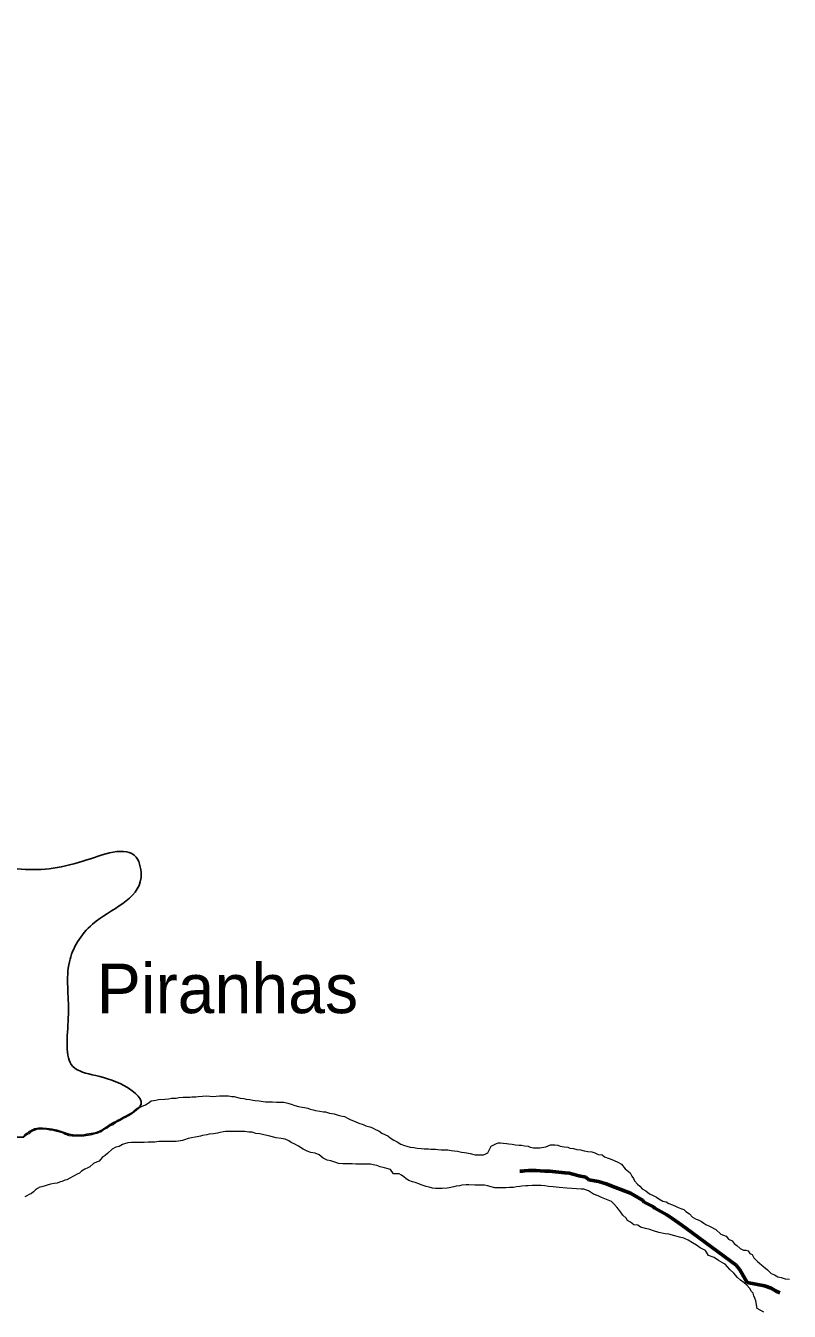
# Model space of a CAD drawing. Extents: x 553962 to 842807, y 8883888 to 9032388.
# Drawn here: x 635696 to 643403, y 8933785 to 8946766 of the extents above; entities that cross this region are included whole.
import ezdxf

# ---------------------------------------------------------------- set-up
doc = ezdxf.new("R2010")
doc.units = 0
doc.header["$LTSCALE"] = 200
doc.linetypes.add('LONG_DASH_SHORT_DASH', pattern=[9.9, 6, -1.2, 1.5, -1.2])
for name, color, linetype, lineweight in [('21', 7, 'Continuous', 25), ('25', 7, 'Continuous', 13), ('7', 7, 'LONG_DASH_SHORT_DASH', 60), ('9', 7, 'Continuous', 90)]:
    doc.layers.add(name, color=color, linetype=linetype, lineweight=lineweight)
doc.layers.add('41', color=7, linetype='Continuous')

msp = doc.modelspace()

# ---------------------------------------------------------------- linework, layer by layer
at = {"layer": '21'}
msp.add_spline([(635677.5, 8935542.3), (635110.6, 8935620.5), (634836.9, 8935855.3), (634709.8, 8936099.8), (634846.6, 8936275.8), (634973.7, 8936735.4), (635032.4, 8937263.6), (634739.1, 8937449.4), (634426.3, 8937517.8), (634700, 8937928.6), (634700, 8938261.1), (634533.8, 8938671.9), (634641.4, 8938906.6), (634768.4, 8938867.5), (634866.2, 8938740.3), (635130.1, 8938750.1), (635188.8, 8938564.3), (635325.6, 8938329.6), (635609.1, 8938251.3), (636273.8, 8938329.6), (636811.4, 8938368.7), (636860.3, 8938163.3), (636371.5, 8937693.9), (636136.9, 8937312.5), (636127.2, 8936784.3), (636156.5, 8936275.8), (636694.1, 8936060.6), (636850.5, 8935855.3), (636821.3, 8935831.4), (636756.6, 8935782.4), (636679.7, 8935742.2), (636611.5, 8935703.8), (636571.3, 8935684.5), (636504.8, 8935639.1), (636420.9, 8935593.6), (636337, 8935576.1), (636239.1, 8935562.1), (636151.7, 8935569.1), (636071.2, 8935593.6), (635990.8, 8935618.1), (635878.9, 8935632.1), (635826.5, 8935633.8), (635795, 8935628.6), (635758.3, 8935612.8), (635712.8, 8935584.8), (635680.9, 8935555.9), (635677.5, 8935542.3)], degree=3, dxfattribs=at)
at = {"layer": '25'}
for points in [[(635685.7, 8935554.4), (635710.8, 8935574.3), (635733.4, 8935581.6), (635756.1, 8935601.5), (635776.2, 8935611.4), (635796.2, 8935616.2), (635818.8, 8935626.1), (635848.8, 8935625.9), (635868.8, 8935625.8), (635908.8, 8935623), (635941.3, 8935617.8), (635973.8, 8935612.6), (636006.2, 8935604.8), (636036.2, 8935597.1), (636073.6, 8935586.9), (636096, 8935574.2), (636130.9, 8935559), (636165.9, 8935556.2), (636185.9, 8935556.1), (636205.9, 8935556), (636243.4, 8935555.7), (636263.5, 8935558.1), (636283.5, 8935557.9), (636303.5, 8935560.3), (636326, 8935562.7), (636346.1, 8935565), (636366.1, 8935569.9), (636398.7, 8935579.7), (636418.7, 8935582.1), (636456.4, 8935599.4), (636479, 8935616.7), (636519.2, 8935636.5), (636539.3, 8935653.9), (636579.5, 8935671.2), (636602.1, 8935691), (636642.3, 8935710.8), (636675, 8935730.6), (636712.6, 8935747.9), (636737.7, 8935762.7), (636770.4, 8935785.1), (636793.1, 8935802.4), (636835.8, 8935834.7), (636863.5, 8935852), (636906.1, 8935869.3), (636941.3, 8935891.6), (636964, 8935908.9), (637009, 8935916.2), (637036.6, 8935923.5), (637099.2, 8935928.1), (637136.7, 8935930.3), (637169.2, 8935935.1), (637214.3, 8935937.3), (637241.8, 8935942.2), (637284.4, 8935946.9), (637304.4, 8935946.8), (637351.9, 8935946.4), (637374.4, 8935948.8), (637412, 8935951.1), (637437, 8935953.4), (637479.5, 8935955.6), (637524.6, 8935960.3), (637584.6, 8935954.9), (637652.2, 8935962), (637672.2, 8935961.8), (637694.7, 8935961.7), (637719.7, 8935961.5), (637742.2, 8935958.9), (637777.1, 8935953.6), (637799.7, 8935953.5), (637824.6, 8935945.8), (637859.6, 8935938.1), (637897, 8935932.8), (637922, 8935927.6), (637959.5, 8935922.4), (637989.5, 8935917.2), (638012, 8935914.5)], [(638012, 8935914.5), (638051.9, 8935909.3), (638091.9, 8935904), (638116.9, 8935901.3), (638154.4, 8935901.1), (638186.9, 8935898.3), (638226.9, 8935895.6), (638259.4, 8935895.4), (638281.9, 8935895.2), (638301.9, 8935895.1), (638341.9, 8935887.3), (638376.8, 8935874.6), (638414.2, 8935861.8), (638449.2, 8935851.6), (638486.6, 8935846.3), (638509.1, 8935841.1), (638544.1, 8935835.9), (638566.5, 8935825.7), (638599, 8935820.5), (638621.5, 8935812.9), (638663.9, 8935805.1), (638701.4, 8935799.8), (638721.4, 8935799.7), (638761.3, 8935786.9), (638808.8, 8935779.1), (638851.2, 8935763.8), (638891.1, 8935753.5), (638913.6, 8935750.8), (638951, 8935733.1), (638978.4, 8935717.9), (639020.8, 8935700.1), (639058.2, 8935684.8), (639103.1, 8935669.5), (639130.5, 8935656.8), (639170.4, 8935646.5), (639195.4, 8935636.3), (639232.7, 8935618.6), (639260.2, 8935605.8), (639290, 8935583.1), (639327.4, 8935565.3), (639349.8, 8935555.2), (639374.7, 8935535), (639412, 8935512.2), (639444.4, 8935494.5), (639481.7, 8935471.7), (639519.2, 8935458.9), (639544.1, 8935451.3), (639576.6, 8935443.5), (639614, 8935438.3), (639646.5, 8935433.1), (639686.5, 8935427.8), (639719, 8935425.1), (639739, 8935424.9), (639761.5, 8935424.8), (639784, 8935422.1), (639814, 8935421.9), (639834, 8935421.8), (639856.5, 8935419.1), (639889, 8935416.4), (639921.5, 8935413.7), (639956.5, 8935413.5), (639991.5, 8935408.2), (640021.5, 8935405.5), (640053.9, 8935400.3), (640093.9, 8935392.5), (640126.4, 8935389.8), (640148.9, 8935384.7), (640183.8, 8935376.9), (640233.7, 8935364.2), (640316.3, 8935366), (640339.2, 8935375.1), (640361.5, 8935385.8), (640394.5, 8935450.6), (640447.2, 8935480.3), (640467.3, 8935485.2), (640487.3, 8935485.1), (640514.8, 8935482.4), (640549.8, 8935479.7), (640572.2, 8935474.5), (640607.2, 8935471.8), (640639.7, 8935466.5), (640677.2, 8935463.8), (640699.7, 8935461.1), (640732.2, 8935455.9), (640767.1, 8935450.7), (640789.6, 8935440.5), (640822, 8935435.3), (640842.1, 8935435.2), (640864.6, 8935435), (640884.6, 8935434.9), (640947.2, 8935447), (640994.9, 8935466.7), (641014.9, 8935466.6), (641037.4, 8935466.4), (641067.3, 8935461.2), (641089.8, 8935453.6), (641132.3, 8935445.8), (641167.2, 8935440.5), (641189.7, 8935432.8), (641224.7, 8935427.6), (641259.6, 8935419.9)], [(638992.5, 8935272.2), (638970, 8935272.3), (638925, 8935272.6), (638897.5, 8935275.3), (638855, 8935278.1), (638825, 8935285.8), (638777.6, 8935303.6), (638737.7, 8935311.4), (638700.3, 8935331.7), (638658.1, 8935364.5), (638618.2, 8935382.3), (638573.2, 8935387.6), (638535.8, 8935402.8), (638495.9, 8935423.1), (638451.1, 8935451), (638413.8, 8935471.2), (638376.4, 8935489), (638351.5, 8935506.7), (638314.1, 8935522), (638274.1, 8935529.8), (638224.2, 8935537.6), (638161.8, 8935553), (638086.8, 8935568.6), (638059.4, 8935576.2), (638019.4, 8935581.5), (637982, 8935591.8), (637947, 8935594.5), (637907, 8935599.8), (637884.5, 8935599.9), (637847, 8935600.2), (637827, 8935600.3), (637792, 8935600.5), (637754.5, 8935600.8), (637714.4, 8935601.1), (637691.9, 8935596.2), (637654.3, 8935588.9), (637631.8, 8935584.1), (637591.7, 8935576.8), (637549.2, 8935574.6), (637524.1, 8935567.3), (637481.5, 8935560), (637461.5, 8935552.7), (637426.4, 8935547.9), (637406.4, 8935543), (637371.3, 8935535.7), (637336.2, 8935528.4), (637298.6, 8935516.2), (637278.5, 8935508.8), (637238.5, 8935504.1), (637215.9, 8935499.2), (637180.9, 8935499.4), (637135.9, 8935499.7), (637105.9, 8935499.9), (637063.4, 8935500.2), (637040.8, 8935497.9), (637000.8, 8935493.1), (636955.8, 8935490.9), (636930.8, 8935491.1), (636890.7, 8935488.8), (636868.2, 8935489), (636830.7, 8935489.2), (636810.7, 8935489.4), (636780.7, 8935489.6), (636760.7, 8935489.7), (636725.6, 8935484.9), (636693, 8935475.1), (636673, 8935467.8), (636640.3, 8935447.9), (636605.2, 8935443.2), (636567.6, 8935420.9), (636524.7, 8935381.1), (636499.6, 8935358.7), (636466.9, 8935336.4), (636436.6, 8935301.6), (636416.5, 8935294.2), (636378.9, 8935276.9), (636343.6, 8935244.6), (636323.5, 8935234.7), (636293.4, 8935219.9), (636260.8, 8935200.1), (636238.1, 8935180.2), (636215.5, 8935167.8), (636180.3, 8935148.1), (636142.7, 8935128.3), (636112.5, 8935110.9), (636092.5, 8935108.6), (636069.9, 8935098.7), (636037.3, 8935088.9), (636014.7, 8935079.1), (635982.2, 8935074.3), (635947.1, 8935067), (635912, 8935059.7), (635892, 8935052.3), (635859.4, 8935042.5), (635839.3, 8935037.7), (635816.7, 8935025.3), (635794.1, 8935010.4), (635773.9, 8934990.5), (635753.8, 8934975.6), (635731.2, 8934963.3), (635708.6, 8934950.9)], [(641259.6, 8935419.9), (641294.6, 8935414.6), (641334.5, 8935404.4), (641369.5, 8935399.1), (641409.5, 8935393.8), (641441.9, 8935383.6), (641474.3, 8935368.4), (641514.3, 8935363.1), (641536.7, 8935345.4), (641574.1, 8935330.2), (641596.6, 8935325), (641636.4, 8935307.2), (641673.8, 8935289.5), (641708.7, 8935271.7), (641748.3, 8935223.9), (641798.1, 8935183.5), (641812.8, 8935148.3), (641832.6, 8935125.7), (641842.5, 8935100.6), (641872.2, 8935067.8), (641894.6, 8935047.7), (641916.9, 8935022.5), (641954.2, 8935002.2), (641994, 8934971.9), (642028.9, 8934954.1), (642063.8, 8934936.4), (642086.2, 8934918.7), (642126, 8934898.4), (642161, 8934890.7), (642188.4, 8934873), (642225.8, 8934860.2), (642260.7, 8934842.4), (642283.1, 8934832.3), (642318, 8934819.5), (642340.5, 8934811.9), (642357.8, 8934791.7), (642395.2, 8934769), (642427.4, 8934736.2), (642462.3, 8934715.9), (642484.8, 8934708.3), (642517.1, 8934690.5), (642539.5, 8934675.4), (642561.9, 8934660.2), (642604.3, 8934642.4), (642661.6, 8934609.5), (642711.2, 8934564.1), (642766.1, 8934543.7), (642790.9, 8934513.5), (642825.8, 8934495.7), (642845.6, 8934470.6), (642875.5, 8934450.3), (642907.7, 8934417.6), (642942.6, 8934402.3), (642965.1, 8934402.2), (642987.6, 8934394.5), (643004.9, 8934366.9), (643027.3, 8934356.7), (643044.6, 8934324), (643084.3, 8934286.2), (643146.4, 8934233.2), (643183.7, 8934202.9), (643221, 8934167.7), (643253.4, 8934152.4), (643288.2, 8934132.2), (643323.2, 8934124.4), (643363.1, 8934114.1), (643405.6, 8934108.8)], [(642690, 8934297.2), (642645.2, 8934327.5), (642587.9, 8934347.9), (642556.4, 8934400.2), (642504.8, 8934424.3), (642466.9, 8934451.8), (642425.6, 8934475.9), (642384.3, 8934503.4), (642339.5, 8934524.1), (642294.8, 8934534.4), (642294.8, 8934534.4), (642246.6, 8934548.2), (642188.1, 8934561.9), (642151.8, 8934566.1), (642086.9, 8934579), (642032, 8934596.9), (641994.6, 8934612.2), (641952.2, 8934620), (641902.2, 8934635.3), (641874.9, 8934653.1), (641834.9, 8934658.3), (641800.1, 8934686.1), (641770.2, 8934701.3), (641755.4, 8934726.4), (641723.1, 8934756.7), (641698.3, 8934789.4), (641681, 8934817.1), (641663.7, 8934837.2), (641628.9, 8934872.5), (641609.1, 8934892.6), (641558.1, 8934912.8), (641506.5, 8934933.5), (641473.6, 8934950.3), (641426.3, 8934968.1), (641376.5, 8935001), (641329.1, 8935016.3), (641301.6, 8935019), (641254.1, 8935021.8), (641209.1, 8935024.7), (641159.1, 8935027.5), (641081.6, 8935035.5), (641021.6, 8935040.9), (640971.7, 8935046.2), (640936.7, 8935051.5), (640899.2, 8935054.2), (640864.2, 8935054.5), (640841.7, 8935054.6), (640806.6, 8935054.8), (640769.1, 8935052.6), (640744.1, 8935050.3), (640704, 8935048), (640684, 8935043.2), (640649, 8935040.9), (640621.4, 8935036.1), (640578.9, 8935033.8), (640543.8, 8935031.6), (640498.8, 8935031.8), (640471.3, 8935032), (640451.3, 8935032.2), (640431.3, 8935032.3), (640393.9, 8935042.6), (640358.9, 8935052.8), (640326.5, 8935058), (640229.1, 8935058.3), (640168.9, 8935061.6), (640141.4, 8935061.8), (640098.9, 8935059.5), (640076.3, 8935052.2), (640041.2, 8935047.4), (640016.2, 8935040.1), (639971.1, 8935032.8), (639951.1, 8935028), (639898.5, 8935025.8), (639856, 8935026.1), (639833.5, 8935026.2), (639801, 8935029), (639768.6, 8935039.2), (639738.6, 8935044.4), (639708.7, 8935054.6), (639686.2, 8935062.3), (639663.8, 8935072.4), (639628.9, 8935085.2), (639601.4, 8935090.4), (639564, 8935105.6), (639536.6, 8935120.8), (639511.7, 8935141), (639489.3, 8935158.7), (639464.5, 8935173.9), (639409.4, 8935171.8), (639379.8, 8935217), (639342.3, 8935227.3), (639317.4, 8935234.9), (639274.9, 8935242.7), (639240, 8935255.5), (639202.5, 8935263.2), (639177.6, 8935270.9), (639125.1, 8935271.3), (639090, 8935271.5), (639050, 8935271.8), (639030, 8935271.9), (638992.5, 8935272.2)], [(635708.6, 8934950.9), (635686, 8934941)], [(643148, 8933777.6), (643078.2, 8933813.1), (643066.3, 8933890.8), (643056.5, 8933918.4), (643046.7, 8933941), (643039.3, 8933966.1), (643022, 8933986.2), (643004.7, 8934016.4), (642970, 8934051.7), (642947.6, 8934071.8), (642910.3, 8934099.6), (642880.5, 8934127.3), (642842.1, 8934169.7), (642842.1, 8934169.7), (642804.3, 8934207.6), (642755, 8934260.3), (642734.8, 8934269.3), (642690, 8934297.2)]]:
    msp.add_lwpolyline(points, dxfattribs=at)
at = {"layer": '7'}
for points in [[(641349.5, 8935138.5), (641279.6, 8935153.8), (641232.2, 8935166.6), (641182.2, 8935179.4), (641137.2, 8935182.1), (641014.8, 8935197.8), (640987.4, 8935200.4), (640937.4, 8935200.7), (640887.4, 8935203.5), (640847.4, 8935206.2), (640824.9, 8935206.3), (640794.9, 8935206.5), (640772.4, 8935206.6), (640732.4, 8935204.3), (640707.4, 8935199.4), (640683.2, 8935198.4)], [(643306.9, 8933971.4), (643271.7, 8933987.2), (643222, 8934017.5), (643154.6, 8934040.4), (642977.3, 8934076.3), (642905.7, 8934204.3), (642868.5, 8934249.6), (642368.5, 8934617.6), (642318.7, 8934652.9), (642216.7, 8934723.5), (642166.9, 8934758.8), (642137, 8934776.5), (642047.4, 8934827), (642025, 8934842.1), (641937.8, 8934885.1), (641922.9, 8934907.7), (641800.9, 8934978.4), (641648.8, 8935034.3), (641556.5, 8935072.3), (641479.2, 8935095.2), (641381.8, 8935110.8), (641349.5, 8935138.5)]]:
    msp.add_lwpolyline(points, dxfattribs=at)
at = {"layer": '9'}
msp.add_spline([(637260.6, 8972975.8), (641524.5, 8971056.2), (652526.1, 8965412.7), (653164.3, 8965062.8), (670790.5, 8953770.1), (686194, 8943929.9), (696283.3, 8937647.1)], degree=3, dxfattribs=at)

# ---------------------------------------------------------------- texts
at = {"layer": '41'}
msp.add_text('Piranhas', height=500, dxfattribs=at).set_placement((636412.8, 8936794.9))

doc.saveas('drawing.dxf')
